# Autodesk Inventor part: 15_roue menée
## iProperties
Shininess: 20.0
Length Units: 11270
Angle Units: 11279
Time Units: 11290
Mass Units: 11283
Length Display Precision: 3
Angle Display Precision: 2
Created: 2000-10
Part Number: 15_roue menée
Material: Par défaut
Document SubType Name: Modélisation
Density: 0.0
Volumn: 0.0
Area: 0.0
PropertySet Name: Model Information
Control State: 0
Master: False
Checked Out: False
Author: Laurent GAUTHERON
